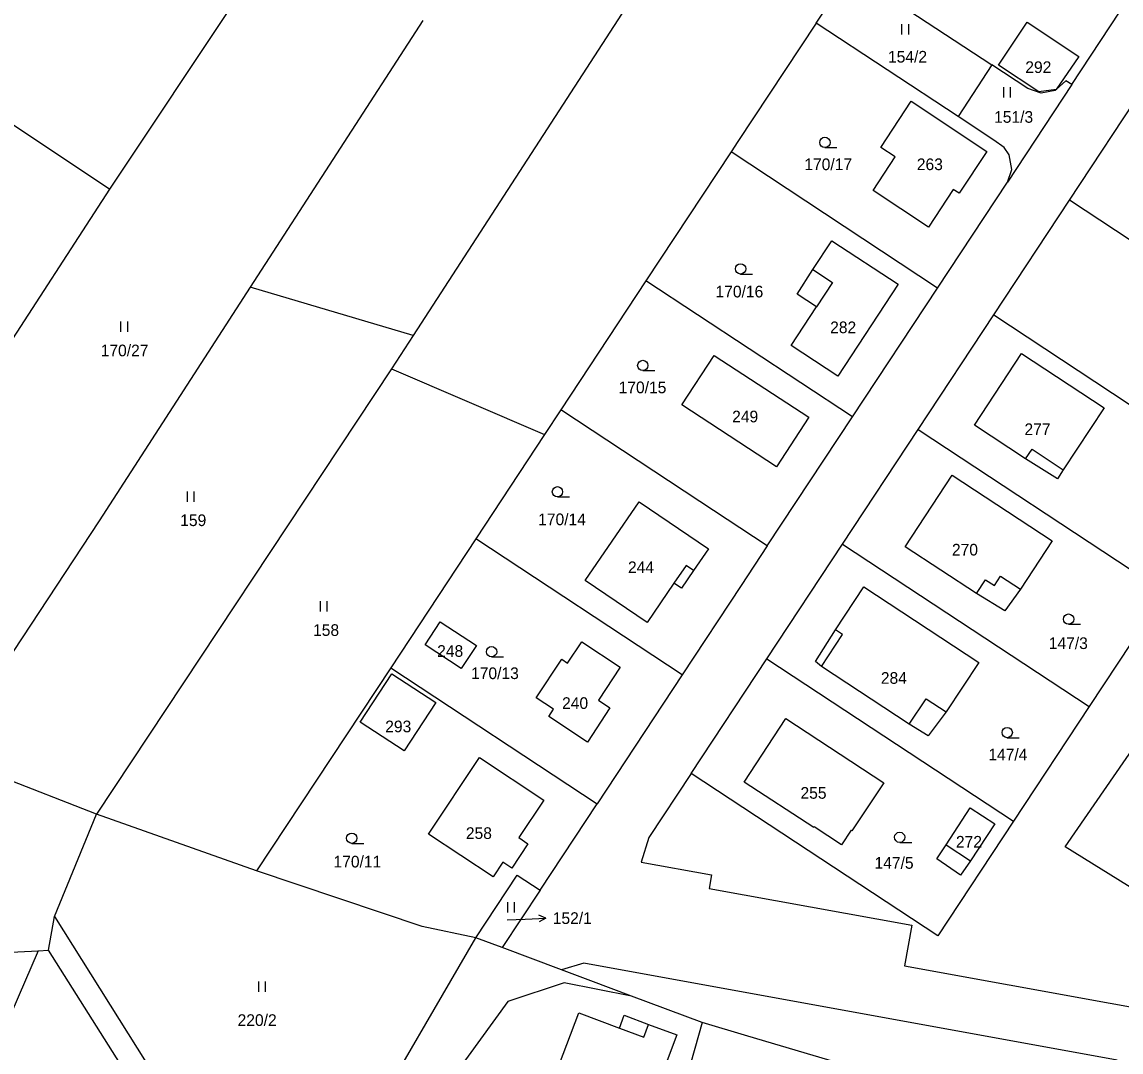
# Model space of a CAD drawing. Extents: x -747333 to -743907, y -1134120 to -1130051.
# Drawn here: x -746642.5 to -746482.5, y -1131946.1 to -1131796 of the extents above; entities that cross this region are included whole.
import ezdxf

# ---------------------------------------------------------------- set-up
doc = ezdxf.new("R2010")
doc.units = 0
for name, color, linetype in [('Hranice parcel', 7, 'Continuous'), ('Parcelní čísla', 7, 'Continuous'), ('Pop  PČ popisy', 7, 'Continuous'), ('Vnitřní kresba', 7, 'Continuous'), ('Značky kultur', 7, 'Continuous')]:
    doc.layers.add(name, color=color, linetype=linetype)

msp = doc.modelspace()

# ---------------------------------------------------------------- linework, layer by layer
at = {"layer": 'Hranice parcel'}
for p, q in [((-746629.7, -1131820.37), (-746604.57, -1131782.51)), ((-746526.88, -1131796.16), (-746521.93, -1131788.64)), ((-746521.93, -1131788.64), (-746501.28, -1131802.26)), ((-746489.67, -1131805.13), (-746478.1, -1131787.6)), ((-746584.14, -1131795.8), (-746609.27, -1131834.66)), ((-746506.22, -1131809.78), (-746526.88, -1131796.16)), ((-746501.28, -1131802.26), (-746506.22, -1131809.78)), ((-746496.04, -1131805.72), (-746501.28, -1131802.26)), ((-746489.67, -1131805.13), (-746499.03, -1131819.32)), ((-746650.27, -1131806.65), (-746629.7, -1131820.37)), ((-746490, -1131821.98), (-746478.99, -1131805.28)), ((-746539.27, -1131814.94), (-746551.66, -1131833.72)), ((-746509.21, -1131834.76), (-746539.27, -1131814.94)), ((-746509.21, -1131834.76), (-746499.03, -1131819.32)), ((-746668.22, -1131879.72), (-746629.7, -1131820.37)), ((-746501.01, -1131838.68), (-746490, -1131821.98)), ((-746454.1, -1131845.66), (-746490, -1131821.98)), ((-746551.66, -1131833.72), (-746564.05, -1131852.51)), ((-746521.6, -1131853.55), (-746551.66, -1131833.72)), ((-746585.55, -1131841.66), (-746609.27, -1131834.66)), ((-746521.6, -1131853.55), (-746509.21, -1131834.76)), ((-746512.02, -1131855.37), (-746501.01, -1131838.68)), ((-746501.01, -1131838.68), (-746465.11, -1131862.35)), ((-746585.55, -1131841.66), (-746588.71, -1131846.53)), ((-746588.71, -1131846.53), (-746631.67, -1131911.42)), ((-746588.71, -1131846.53), (-746566.41, -1131856.09)), ((-746564.05, -1131852.51), (-746566.41, -1131856.09)), ((-746533.99, -1131872.33), (-746521.6, -1131853.55)), ((-746566.41, -1131856.09), (-746576.43, -1131871.29)), ((-746523.03, -1131872.07), (-746512.02, -1131855.37)), ((-746512.02, -1131855.37), (-746476.13, -1131879.05)), ((-746576.43, -1131871.29), (-746588.82, -1131890.07)), ((-746546.37, -1131891.11), (-746576.43, -1131871.29)), ((-746534.04, -1131888.76), (-746523.03, -1131872.07)), ((-746523.03, -1131872.07), (-746487.14, -1131895.74)), ((-746476.13, -1131879.05), (-746487.14, -1131895.74)), ((-746545.06, -1131905.46), (-746534.04, -1131888.76)), ((-746534.04, -1131888.76), (-746498.15, -1131912.44)), ((-746588.82, -1131890.07), (-746608.35, -1131919.68)), ((-746588.82, -1131890.07), (-746558.76, -1131909.9)), ((-746546.37, -1131891.11), (-746558.76, -1131909.9)), ((-746487.14, -1131895.74), (-746498.15, -1131912.44)), ((-746631.67, -1131911.42), (-746653.72, -1131902.76)), ((-746567.07, -1131922.49), (-746558.76, -1131909.9)), ((-746637.77, -1131926.3), (-746631.67, -1131911.42)), ((-746608.35, -1131919.68), (-746631.67, -1131911.42)), ((-746576.43, -1131929.41), (-746570.41, -1131920.29)), ((-746570.41, -1131920.29), (-746567.07, -1131922.49)), ((-746567.07, -1131922.49), (-746572.59, -1131930.85)), ((-746638.63, -1131931.22), (-746637.77, -1131926.3)), ((-746637.77, -1131926.3), (-746601.69, -1131983.7)), ((-746572.59, -1131930.85), (-746576.43, -1131929.41)), ((-746646.39, -1131931.6), (-746640.16, -1131931.3)), ((-746640.16, -1131931.3), (-746638.63, -1131931.22)), ((-746596.68, -1131997.54), (-746638.63, -1131931.22)), ((-746563.94, -1131934.09), (-746572.59, -1131930.85)), ((-746560.7, -1131933.13), (-746563.94, -1131934.09)), ((-746483.07, -1131947.25), (-746560.7, -1131933.13)), ((-746553.77, -1131937.9), (-746563.57, -1131935.97)), ((-746543.47, -1131941.76), (-746553.77, -1131937.9)), ((-746543.47, -1131941.76), (-746546.13, -1131951.07))]:
    msp.add_line(p, q, dxfattribs=at)
for points in [[(-746417.71, -1131586.04), (-746453.14, -1131641.65), (-746533.7, -1131761.53), (-746550, -1131786.81), (-746585.55, -1131841.66)], [(-746526.88, -1131796.16), (-746538.26, -1131813.41), (-746539.27, -1131814.94)], [(-746494.46, -1131806.19), (-746500.31, -1131802.29), (-746496.17, -1131796.01), (-746488.63, -1131801.02), (-746491.91, -1131805.82), (-746494.46, -1131806.19)], [(-746489.67, -1131805.13), (-746490.5, -1131804.58), (-746491.91, -1131805.82), (-746492.08, -1131805.97), (-746494.1, -1131806.37), (-746496.04, -1131805.72)], [(-746510.52, -1131825.88), (-746518.59, -1131820.56), (-746515.39, -1131815.67), (-746517.47, -1131814.31), (-746513.02, -1131807.53), (-746502, -1131814.86), (-746506.06, -1131820.92), (-746506.91, -1131820.39), (-746510.52, -1131825.88)], [(-746499.03, -1131819.32), (-746498.38, -1131817.52), (-746498.76, -1131815.38), (-746499.51, -1131814.31), (-746501, -1131813.23), (-746506.22, -1131809.78)], [(-746523.73, -1131847.59), (-746530.53, -1131843.14), (-746526.83, -1131837.5), (-746529.63, -1131835.64), (-746527.36, -1131832.06), (-746524.58, -1131827.88), (-746514.94, -1131834.22), (-746523.73, -1131847.59)], [(-746609.27, -1131834.66), (-746631.27, -1131868.67), (-746653.72, -1131902.76)], [(-746527.94, -1131853.59), (-746532.65, -1131860.81), (-746546.42, -1131851.79), (-746541.73, -1131844.57), (-746527.94, -1131853.59)], [(-746491.75, -1131862.56), (-746496.38, -1131859.65), (-746503.84, -1131854.73), (-746496.98, -1131844.32), (-746484.96, -1131852.24), (-746490.9, -1131861.24), (-746491.75, -1131862.56)], [(-746533.99, -1131872.33), (-746543.81, -1131865.86), (-746564.05, -1131852.51)], [(-746513.9, -1131872.45), (-746507.05, -1131862.03), (-746492.5, -1131871.6), (-746497.13, -1131878.62), (-746499.39, -1131881.78), (-746503.53, -1131879.26), (-746513.9, -1131872.45)], [(-746544.71, -1131875.9), (-746546.5, -1131878.51), (-746547.57, -1131877.78), (-746551.46, -1131883.51), (-746560.48, -1131877.38), (-746552.65, -1131865.89), (-746542.56, -1131872.76), (-746544.71, -1131875.9)], [(-746533.99, -1131872.33), (-746537.79, -1131878.09), (-746546.37, -1131891.11)], [(-746526.08, -1131889.91), (-746526.95, -1131889.18), (-746524.08, -1131884.54), (-746519.95, -1131878.28), (-746503.2, -1131889.33), (-746507.95, -1131896.52), (-746510.54, -1131899.99), (-746513.32, -1131898.32), (-746526.08, -1131889.91)], [(-746578.54, -1131890.2), (-746583.8, -1131886.76), (-746581.61, -1131883.41), (-746576.33, -1131886.85), (-746578.54, -1131890.2)], [(-746567.62, -1131894.48), (-746563.91, -1131888.85), (-746563.09, -1131889.4), (-746561, -1131886.29), (-746555.4, -1131890.01), (-746558.54, -1131894.79), (-746556.89, -1131895.9), (-746560.17, -1131900.92), (-746565.79, -1131897.18), (-746565.11, -1131896.12), (-746567.62, -1131894.48)], [(-746582.27, -1131895.15), (-746586.87, -1131902.18), (-746593.25, -1131898.01), (-746588.67, -1131890.97), (-746582.27, -1131895.15)], [(-746537.36, -1131906.73), (-746531.27, -1131897.47), (-746517.04, -1131906.83), (-746521.67, -1131913.82), (-746521.78, -1131913.76), (-746523.18, -1131915.87), (-746527.14, -1131913.27), (-746527.21, -1131913.37), (-746537.36, -1131906.73)], [(-746454.36, -1131938.7), (-746469.66, -1131929.19), (-746490.63, -1131916.16), (-746477.5, -1131897.18)], [(-746583.31, -1131914.32), (-746575.9, -1131903.14), (-746566.54, -1131909.35), (-746570.17, -1131914.83), (-746568.83, -1131915.71), (-746571.18, -1131919.26), (-746572.49, -1131918.39), (-746573.92, -1131920.55), (-746583.31, -1131914.32)], [(-746545.06, -1131905.46), (-746551.21, -1131914.79), (-746552.36, -1131918.38), (-746542.1, -1131920.25), (-746542.46, -1131922.22), (-746512.94, -1131927.58), (-746514.01, -1131933.49), (-746468.81, -1131941.71), (-746454.36, -1131938.7)], [(-746498.15, -1131912.44), (-746509.16, -1131929.13), (-746545.06, -1131905.46)], [(-746504.45, -1131910.49), (-746500.88, -1131912.81), (-746504.4, -1131918.2), (-746505.85, -1131920.3), (-746509.31, -1131917.93), (-746507.95, -1131915.87), (-746504.45, -1131910.49)], [(-746576.43, -1131929.41), (-746584.22, -1131927.79), (-746608.35, -1131919.68)], [(-746601.69, -1131983.7), (-746593.05, -1131958.05), (-746576.43, -1131929.41)], [(-746640.16, -1131931.3), (-746678.35, -1132019.74), (-746690.91, -1132050.15), (-746705.38, -1132080.91)], [(-746553.77, -1131937.9), (-746559.67, -1131935.69), (-746563.94, -1131934.09)], [(-746563.57, -1131935.97), (-746571.75, -1131938.7), (-746581.53, -1131952.14), (-746582.49, -1131956.4), (-746583.19, -1131959.53)], [(-746551.26, -1131942.03), (-746547.16, -1131943.56), (-746551.34, -1131954.67), (-746560.74, -1131951.14), (-746562.32, -1131955.31), (-746566.43, -1131953.71), (-746568.84, -1131952.76), (-746567.28, -1131948.71), (-746564.91, -1131949.57), (-746561.44, -1131940.34), (-746555.51, -1131942.57), (-746554.83, -1131940.71), (-746551.26, -1131942.03)], [(-746513.04, -1131950.81), (-746536.83, -1131943.73), (-746543.47, -1131941.76)]]:
    msp.add_lwpolyline(points, dxfattribs=at)
at = {"layer": 'Pop  PČ popisy'}
for p, q in [((-746571.85, -1131926.79), (-746569.22, -1131926.68)), ((-746569.22, -1131926.68), (-746566.221, -1131926.575)), ((-746566.221, -1131926.575), (-746567.239, -1131926.11)), ((-746566.221, -1131926.575), (-746567.204, -1131927.111))]:
    msp.add_line(p, q, dxfattribs=at)
at = {"layer": 'Vnitřní kresba'}
for p, q in [((-746527.36, -1131832.06), (-746524.5, -1131833.96)), ((-746524.5, -1131833.96), (-746526.83, -1131837.5)), ((-746496.38, -1131859.65), (-746495.43, -1131858.22)), ((-746495.43, -1131858.22), (-746490.9, -1131861.24)), ((-746545.8, -1131875.16), (-746547.57, -1131877.78)), ((-746544.71, -1131875.9), (-746545.8, -1131875.16)), ((-746500.92, -1131878.11), (-746500.02, -1131876.73)), ((-746500.02, -1131876.73), (-746497.13, -1131878.62)), ((-746503.53, -1131879.26), (-746502.24, -1131877.27)), ((-746502.24, -1131877.27), (-746500.92, -1131878.11)), ((-746523.02, -1131885.25), (-746524.08, -1131884.54)), ((-746526.08, -1131889.91), (-746523.02, -1131885.25)), ((-746513.32, -1131898.32), (-746510.87, -1131894.59)), ((-746510.87, -1131894.59), (-746507.95, -1131896.52)), ((-746507.95, -1131915.87), (-746504.4, -1131918.2)), ((-746555.51, -1131942.57), (-746551.96, -1131943.91)), ((-746551.96, -1131943.91), (-746551.26, -1131942.03))]:
    msp.add_line(p, q, dxfattribs=at)
at = {"layer": 'Značky kultur'}
for p, q in [((-746514.381, -1131797.84), (-746514.381, -1131796.34)), ((-746513.38, -1131797.84), (-746513.38, -1131796.34)), ((-746499.571, -1131807.01), (-746499.571, -1131805.51)), ((-746498.57, -1131807.01), (-746498.57, -1131805.51)), ((-746525.593, -1131814.3), (-746523.843, -1131814.3)), ((-746537.873, -1131832.72), (-746536.123, -1131832.72)), ((-746628.101, -1131841.16), (-746628.101, -1131839.66)), ((-746627.1, -1131841.16), (-746627.1, -1131839.66)), ((-746552.113, -1131846.79), (-746550.363, -1131846.79)), ((-746618.411, -1131865.89), (-746618.411, -1131864.39)), ((-746617.41, -1131865.89), (-746617.41, -1131864.39)), ((-746564.543, -1131865.19), (-746562.793, -1131865.19)), ((-746599.051, -1131881.89), (-746599.051, -1131880.39)), ((-746598.05, -1131881.89), (-746598.05, -1131880.39)), ((-746490.113, -1131883.74), (-746488.363, -1131883.74)), ((-746574.123, -1131888.49), (-746572.373, -1131888.49)), ((-746499.053, -1131900.27), (-746497.303, -1131900.27)), ((-746514.713, -1131915.53), (-746512.963, -1131915.53)), ((-746594.493, -1131915.66), (-746592.743, -1131915.66)), ((-746571.771, -1131925.71), (-746571.771, -1131924.21)), ((-746570.77, -1131925.71), (-746570.77, -1131924.21)), ((-746608.041, -1131937.3), (-746608.041, -1131935.8)), ((-746607.04, -1131937.3), (-746607.04, -1131935.8))]:
    msp.add_line(p, q, dxfattribs=at)
for centre in [(-746525.593, -1131813.55), (-746537.873, -1131831.97), (-746552.113, -1131846.04), (-746564.543, -1131864.44), (-746490.113, -1131882.99), (-746574.123, -1131887.74), (-746499.053, -1131899.52), (-746594.493, -1131914.91), (-746514.713, -1131914.78)]:
    msp.add_circle(centre, 0.75, dxfattribs=at)

# ---------------------------------------------------------------- texts
at = {"layer": 'Parcelní čísla'}
for s, p in [('154/2', (-746516.413, -1131801.92)), ('292', (-746496.424, -1131803.44)), ('151/3', (-746500.963, -1131810.69)), ('170/17', (-746528.595, -1131817.59)), ('263', (-746512.214, -1131817.59)), ('170/16', (-746541.525, -1131836.13)), ('282', (-746524.834, -1131841.34)), ('170/27', (-746631.04, -1131844.71)), ('170/15', (-746555.635, -1131850.09)), ('249', (-746539.104, -1131854.33)), ('277', (-746496.544, -1131856.19)), ('170/14', (-746567.345, -1131869.31)), ('159', (-746619.46, -1131869.44)), ('270', (-746507.104, -1131873.73)), ('244', (-746554.274, -1131876.29)), ('158', (-746600.12, -1131885.44)), ('248', (-746582.054, -1131888.49)), ('147/3', (-746493.003, -1131887.35)), ('170/13', (-746577.115, -1131891.73)), ('284', (-746517.454, -1131892.42)), ('240', (-746563.864, -1131896.08)), ('293', (-746589.614, -1131899.48)), ('147/4', (-746501.803, -1131903.57)), ('255', (-746529.154, -1131909.16)), ('258', (-746577.874, -1131915.02)), ('272', (-746506.524, -1131916.28)), ('170/11', (-746597.145, -1131919.17)), ('147/5', (-746518.373, -1131919.36)), ('152/1', (-746565.22, -1131927.4)), ('220/2', (-746611.11, -1131942.26))]:
    msp.add_text(s, height=1.7, dxfattribs=at).set_placement(p)

doc.saveas('drawing.dxf')
